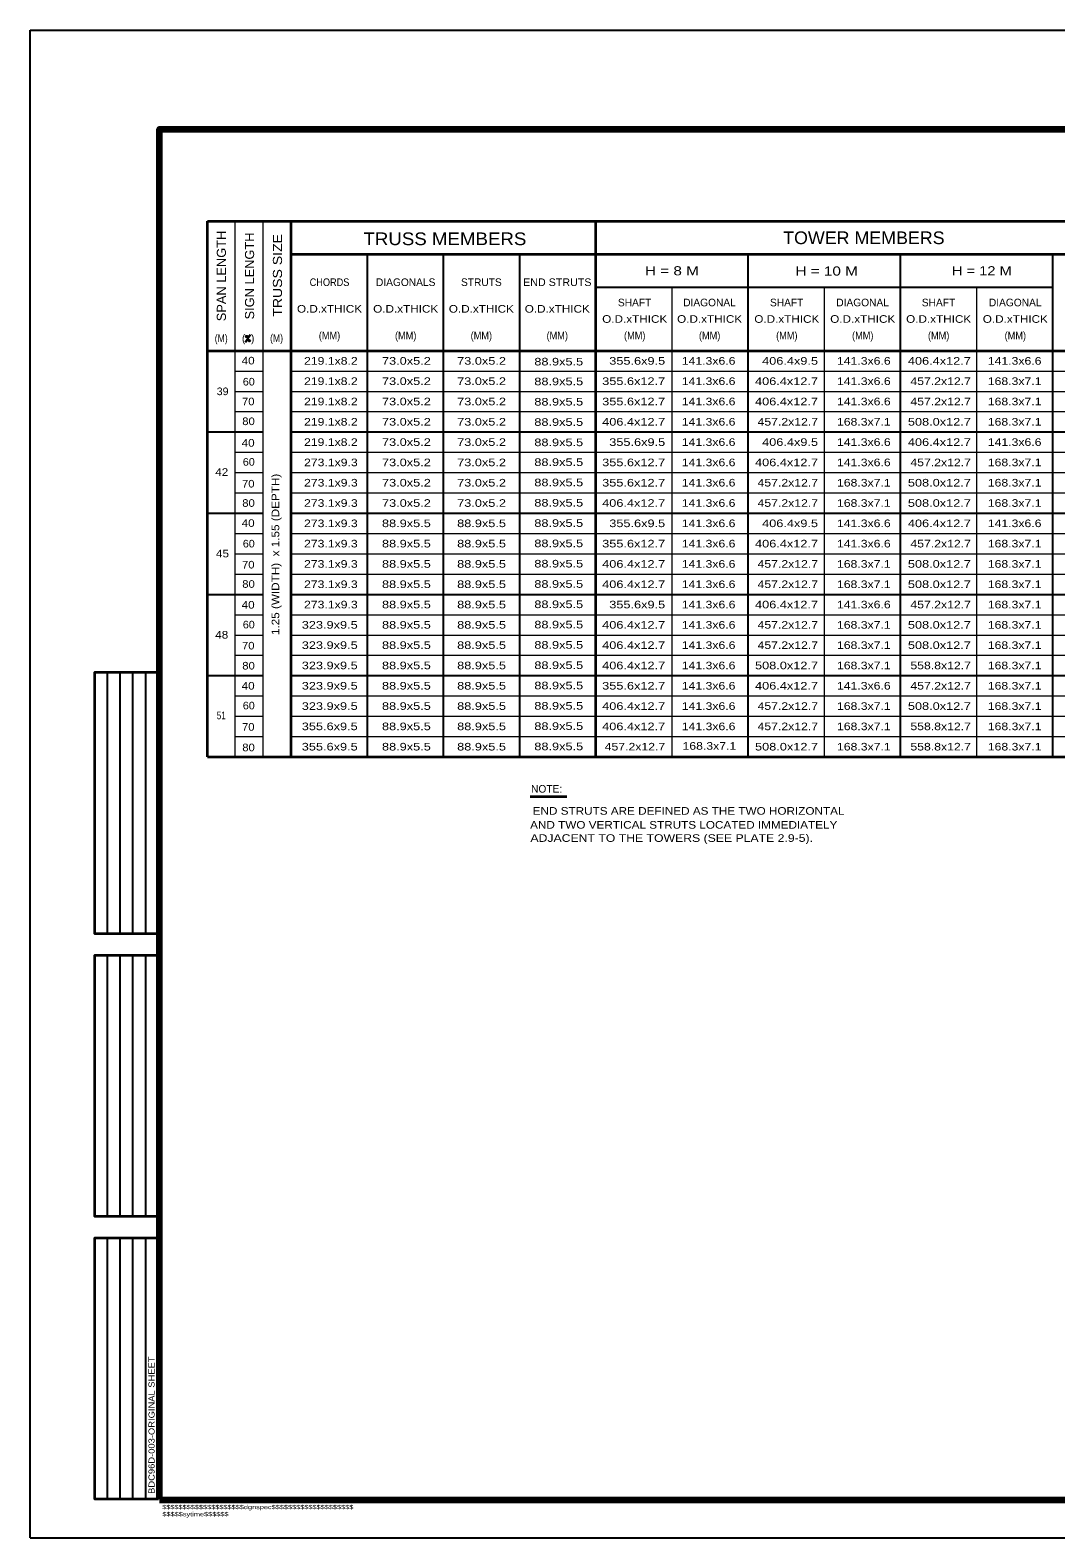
# Model space of a CAD drawing. Extents: x 312601.858 to 312602.699, y 144420.109 to 144420.703.
# Drawn here: x 312601.858 to 312602.262, y 144420.109 to 144420.703 of the extents above; entities that cross this region are included whole.
import ezdxf
from ezdxf.enums import TextEntityAlignment as Align

# ---------------------------------------------------------------- set-up
doc = ezdxf.new("R2010")
doc.units = 0
doc.header["$LTSCALE"] = 0.0012
for name, color, linetype, lineweight in [('1', 7, 'Continuous', 13), ('2', 7, 'Continuous', 35), ('39', 7, 'Continuous', 35), ('60', 7, 'Continuous', 25)]:
    doc.layers.add(name, color=color, linetype=linetype, lineweight=lineweight)

msp = doc.modelspace()

# ---------------------------------------------------------------- linework, layer by layer
at = {"layer": '1', "lineweight": 35}
for p, q in [((312601.9277, 144420.417), (312601.9277, 144420.628)), ((312601.9277, 144420.628), (312602.6681, 144420.628)), ((312601.9607, 144420.417), (312601.9607, 144420.628)), ((312602.0807, 144420.417), (312602.0807, 144420.628)), ((312601.9607, 144420.615), (312602.6357, 144420.615)), ((312601.9277, 144420.577), (312602.6681, 144420.577)), ((312601.9277, 144420.417), (312602.6681, 144420.417))]:
    msp.add_line(p, q, dxfattribs=at)
at = {"layer": '1'}
for p, q in [((312601.9387, 144420.417), (312601.9387, 144420.628)), ((312601.9497, 144420.417), (312601.9497, 144420.628)), ((312602.1107, 144420.417), (312602.1107, 144420.602)), ((312602.1707, 144420.417), (312602.1707, 144420.602)), ((312602.2307, 144420.417), (312602.2307, 144420.602)), ((312602.0357, 144420.577), (312602.2157, 144420.577)), ((312602.0357, 144420.577), (312602.2157, 144420.577)), ((312601.9387, 144420.569), (312601.9497, 144420.569)), ((312601.9607, 144420.569), (312602.6357, 144420.569)), ((312601.9387, 144420.561), (312601.9497, 144420.561)), ((312601.9609, 144420.561), (312602.6357, 144420.561)), ((312601.9387, 144420.553), (312601.9497, 144420.553)), ((312601.9609, 144420.553), (312602.6357, 144420.553)), ((312601.9387, 144420.537), (312601.9497, 144420.537)), ((312601.9387, 144420.537), (312601.949, 144420.537)), ((312601.9609, 144420.537), (312602.6357, 144420.537)), ((312601.9387, 144420.529), (312601.9497, 144420.529)), ((312601.9609, 144420.529), (312602.6357, 144420.529)), ((312601.9387, 144420.521), (312601.9497, 144420.521)), ((312601.9609, 144420.521), (312602.6357, 144420.521)), ((312601.9387, 144420.505), (312601.9497, 144420.505)), ((312601.9609, 144420.505), (312602.6357, 144420.505)), ((312601.9387, 144420.497), (312601.9497, 144420.497)), ((312601.9609, 144420.497), (312602.6357, 144420.497)), ((312601.9387, 144420.489), (312601.9497, 144420.489)), ((312601.9609, 144420.489), (312602.6357, 144420.489)), ((312601.9387, 144420.473), (312601.9497, 144420.473)), ((312601.9609, 144420.473), (312602.6357, 144420.473)), ((312601.9387, 144420.465), (312601.9497, 144420.465)), ((312601.9609, 144420.465), (312602.6357, 144420.465)), ((312601.9387, 144420.457), (312601.9497, 144420.457)), ((312601.9609, 144420.457), (312602.6357, 144420.457)), ((312601.9387, 144420.441), (312601.9497, 144420.441)), ((312601.9609, 144420.441), (312602.6357, 144420.441)), ((312601.9387, 144420.433), (312601.9497, 144420.433)), ((312601.9609, 144420.433), (312602.6357, 144420.433)), ((312601.9387, 144420.425), (312601.9497, 144420.425)), ((312601.9609, 144420.425), (312602.6357, 144420.425))]:
    msp.add_line(p, q, dxfattribs=at)
at = {"layer": '1', "lineweight": 25}
for p, q in [((312601.9907, 144420.417), (312601.9907, 144420.615)), ((312602.0207, 144420.417), (312602.0207, 144420.615)), ((312602.0507, 144420.417), (312602.0507, 144420.615)), ((312602.1407, 144420.417), (312602.1407, 144420.615)), ((312602.2007, 144420.417), (312602.2007, 144420.615)), ((312602.2607, 144420.417), (312602.2607, 144420.615)), ((312602.0807, 144420.602), (312602.2607, 144420.602)), ((312601.9427, 144420.5804), (312601.9447, 144420.5834)), ((312601.9277, 144420.545), (312601.9497, 144420.545)), ((312601.9609, 144420.545), (312602.6357, 144420.545)), ((312601.9277, 144420.513), (312601.9497, 144420.513)), ((312601.9609, 144420.513), (312602.6357, 144420.513)), ((312601.9277, 144420.481), (312601.9497, 144420.481)), ((312601.9609, 144420.481), (312602.6357, 144420.481)), ((312601.9277, 144420.449), (312601.9497, 144420.449)), ((312601.9609, 144420.449), (312602.6357, 144420.449))]:
    msp.add_line(p, q, dxfattribs=at)
for centre in [(312601.9432, 144420.5826), (312601.9442, 144420.581)]:
    msp.add_circle(centre, 0.0003, dxfattribs=at)
at = {"layer": '2'}
msp.add_line((312602.0548, 144420.4014), (312602.0693, 144420.4014), dxfattribs=at)
at = {"layer": '39', "lineweight": 25}
for p, q in [((312601.8579, 144420.7033), (312602.6989, 144420.7033)), ((312601.8579, 144420.1093), (312601.8579, 144420.7033))]:
    msp.add_line(p, q, dxfattribs=at)
msp.add_lwpolyline([(312601.8579, 144420.1093), (312602.6989, 144420.1093), (312602.6989, 144420.7033)], dxfattribs=at)
at = {"layer": '39', "lineweight": 158}
for points in [[(312601.9089, 144420.1243), (312602.6839, 144420.1243), (312602.6839, 144420.6643)], [(312601.9089, 144420.1245), (312601.9089, 144420.6643), (312602.6839, 144420.6643)]]:
    msp.add_lwpolyline(points, dxfattribs=at)
at = {"layer": '60'}
for p, q in [((312601.8884, 144420.3473), (312601.8884, 144420.4503)), ((312601.8934, 144420.3473), (312601.8934, 144420.4503)), ((312601.8984, 144420.3473), (312601.8984, 144420.4503)), ((312601.9035, 144420.3473), (312601.9035, 144420.4503)), ((312601.8884, 144420.2359), (312601.8884, 144420.3389)), ((312601.8934, 144420.2359), (312601.8934, 144420.3389)), ((312601.8984, 144420.2359), (312601.8984, 144420.3389)), ((312601.9035, 144420.2359), (312601.9035, 144420.3389)), ((312601.8884, 144420.1245), (312601.8884, 144420.2275)), ((312601.8934, 144420.1245), (312601.8934, 144420.2275)), ((312601.8984, 144420.1245), (312601.8984, 144420.2275)), ((312601.9035, 144420.1245), (312601.9035, 144420.2275))]:
    msp.add_line(p, q, dxfattribs=at)
at = {"layer": '60', "lineweight": 35}
for points in [[(312601.9085, 144420.3473), (312601.8834, 144420.3473), (312601.8834, 144420.4503), (312601.9085, 144420.4503)], [(312601.9085, 144420.2359), (312601.8834, 144420.2359), (312601.8834, 144420.3389), (312601.9085, 144420.3389)], [(312601.9085, 144420.1245), (312601.8834, 144420.1245), (312601.8834, 144420.2275), (312601.9085, 144420.2275)]]:
    msp.add_lwpolyline(points, dxfattribs=at)

# ---------------------------------------------------------------- texts
at = {"layer": '1'}
for s, height, width, p in [('SPAN LENGTH', 0.0036, 1.05, (312601.935, 144420.60645)), ('SIGN LENGTH', 0.0036, 1.05, (312601.9461, 144420.60645)), ('TRUSS SIZE', 0.0036, 1.15, (312601.9571, 144420.6067)), ('1.25 (WIDTH)  x 1.55 (DEPTH) ', 0.003, 1.15, (312601.956, 144420.4974))]:
    msp.add_text(s, height=height, rotation=90, dxfattribs=dict(at, width=width)).set_placement(p, align=Align.CENTER)
for s, height, width, p in [('TRUSS MEMBERS', 0.005, 1.1, (312602.02125, 144420.6186)), ('TOWER MEMBERS', 0.005, 1.05, (312602.18625, 144420.619)), ('H = 8 M', 0.0036, 1.25, (312602.11065, 144420.6067)), ('H = 10 M', 0.0036, 1.25, (312602.1716, 144420.6066)), ('H = 12 M', 0.0036, 1.2, (312602.2327, 144420.6067)), ('CHORDS', 0.003, 0.9, (312601.9758, 144420.6025)), ('END STRUTS', 0.003, 1.05, (312602.0655, 144420.6025)), ('O.D.xTHICK', 0.003, 1.15, (312601.9758, 144420.592)), ('O.D.xTHICK', 0.003, 1.15, (312602.0058, 144420.592)), ('O.D.xTHICK', 0.003, 1.15, (312602.0356, 144420.592)), ('O.D.xTHICK', 0.003, 1.15, (312602.0655, 144420.592)), ('O.D.xTHICK', 0.003, 1.15, (312602.096, 144420.588)), ('O.D.xTHICK', 0.003, 1.15, (312602.1255, 144420.588)), ('O.D.xTHICK', 0.003, 1.15, (312602.1559, 144420.588)), ('O.D.xTHICK', 0.003, 1.15, (312602.1858, 144420.588)), ('O.D.xTHICK', 0.003, 1.15, (312602.2157, 144420.588)), ('O.D.xTHICK', 0.003, 1.15, (312602.2459, 144420.588)), ('(M)', 0.003, 0.85, (312601.93315, 144420.5804)), ('(M)', 0.003, 0.85, (312601.95495, 144420.5805)), ('(MM)', 0.003, 0.9, (312601.9758, 144420.5815)), ('(MM)', 0.003, 0.9, (312602.0058, 144420.5815)), ('(MM)', 0.003, 0.9, (312602.0356, 144420.5815)), ('(MM)', 0.003, 0.9, (312602.0655, 144420.5815)), ('(MM)', 0.003, 0.9, (312602.096, 144420.5815)), ('(MM)', 0.003, 0.9, (312602.1255, 144420.5815)), ('(MM)', 0.003, 0.9, (312602.1559, 144420.5815)), ('(MM)', 0.003, 0.9, (312602.1858, 144420.5815)), ('(MM)', 0.003, 0.9, (312602.2157, 144420.5815)), ('(MM)', 0.003, 0.9, (312602.2459, 144420.5815)), ('40', 0.003, 1.15, (312601.94375, 144420.5716)), ('141.3x6.6', 0.003, 1.2, (312602.1251, 144420.5715)), ('39', 0.003, 1.05, (312601.9337, 144420.5595)), ('60', 0.003, 1.05, (312601.944, 144420.5633)), ('141.3x6.6', 0.003, 1.2, (312602.1251, 144420.5635)), ('70', 0.003, 1.1, (312601.9438, 144420.5555)), ('141.3x6.6', 0.003, 1.2, (312602.1251, 144420.5555)), ('80', 0.003, 1.1, (312601.9439, 144420.5477)), ('141.3x6.6', 0.003, 1.2, (312602.1251, 144420.5475)), ('40', 0.003, 1.15, (312601.94375, 144420.5392)), ('141.3x6.6', 0.003, 1.2, (312602.1251, 144420.5395)), ('60', 0.003, 1.05, (312601.944, 144420.5317)), ('141.3x6.6', 0.003, 1.2, (312602.1251, 144420.5315)), ('42', 0.003, 1.15, (312601.93335, 144420.5277)), ('70', 0.003, 1.1, (312601.9438, 144420.5231)), ('141.3x6.6', 0.003, 1.2, (312602.1251, 144420.5235)), ('80', 0.003, 1.1, (312601.9439, 144420.5155)), ('141.3x6.6', 0.003, 1.2, (312602.1251, 144420.5155)), ('40', 0.003, 1.15, (312601.94375, 144420.5076)), ('141.3x6.6', 0.003, 1.2, (312602.1251, 144420.5075)), ('45', 0.003, 1.15, (312601.93365, 144420.4956)), ('60', 0.003, 1.05, (312601.944, 144420.4995)), ('141.3x6.6', 0.003, 1.2, (312602.1251, 144420.4995)), ('70', 0.003, 1.1, (312601.9438, 144420.4912)), ('141.3x6.6', 0.003, 1.2, (312602.1251, 144420.4915)), ('80', 0.003, 1.1, (312601.9439, 144420.4836)), ('141.3x6.6', 0.003, 1.2, (312602.1251, 144420.4835)), ('40', 0.003, 1.15, (312601.94375, 144420.4754)), ('141.3x6.6', 0.003, 1.2, (312602.1251, 144420.4755)), ('60', 0.003, 1.05, (312601.944, 144420.4676)), ('141.3x6.6', 0.003, 1.2, (312602.1251, 144420.4675)), ('48', 0.003, 1.15, (312601.93335, 144420.4636)), ('70', 0.003, 1.1, (312601.9438, 144420.4593)), ('141.3x6.6', 0.003, 1.2, (312602.1251, 144420.4595)), ('80', 0.003, 1.1, (312601.9439, 144420.4514)), ('141.3x6.6', 0.003, 1.2, (312602.1251, 144420.4515)), ('40', 0.003, 1.15, (312601.94375, 144420.4435)), ('141.3x6.6', 0.003, 1.2, (312602.1251, 144420.4435)), ('60', 0.003, 1.05, (312601.944, 144420.4357)), ('141.3x6.6', 0.003, 1.2, (312602.1251, 144420.4355)), ('51', 0.003, 0.8, (312601.93315, 144420.4318)), ('70', 0.003, 1.1, (312601.9438, 144420.4273)), ('141.3x6.6', 0.003, 1.2, (312602.1251, 144420.4275)), ('80', 0.003, 1.1, (312601.9439, 144420.4192)), ('168.3x7.1', 0.003, 1.2, (312602.1254, 144420.4198))]:
    msp.add_text(s, height=height, dxfattribs=dict(at, width=width)).set_placement(p, align=Align.CENTER)
for s, p in [('DIAGONALS', (312602.0058, 144420.6025)), ('STRUTS', (312602.0356, 144420.6025)), ('SHAFT', (312602.09595, 144420.5945)), ('DIAGONAL', (312602.12545, 144420.5945)), ('SHAFT', (312602.15585, 144420.5945)), ('DIAGONAL', (312602.18575, 144420.5945)), ('SHAFT', (312602.21565, 144420.5945)), ('DIAGONAL', (312602.24585, 144420.5945)), ('(  )', (312601.94375, 144420.5804)), ('NOTE:', (312602.0613, 144420.4029))]:
    msp.add_text(s, height=0.003, dxfattribs=at).set_placement(p, align=Align.CENTER)
for s, width, p in [('219.1x8.2', 1.2, (312601.9869, 144420.5715)), ('73.0x5.2', 1.25, (312602.0157, 144420.5715)), ('73.0x5.2', 1.25, (312602.0453, 144420.5715)), ('355.6x9.5', 1.25, (312602.108, 144420.5715)), ('406.4x9.5', 1.25, (312602.1682, 144420.5715)), ('141.3x6.6', 1.2, (312602.1968, 144420.5715)), ('406.4x12.7', 1.25, (312602.2284, 144420.5715)), ('141.3x6.6', 1.2, (312602.2562, 144420.5715)), ('219.1x8.2', 1.2, (312601.9869, 144420.5635)), ('73.0x5.2', 1.25, (312602.0157, 144420.5635)), ('73.0x5.2', 1.25, (312602.0453, 144420.5635)), ('355.6x12.7', 1.25, (312602.108, 144420.5635)), ('406.4x12.7', 1.25, (312602.1682, 144420.5635)), ('141.3x6.6', 1.2, (312602.1968, 144420.5635)), ('457.2x12.7', 1.2, (312602.2284, 144420.5635)), ('168.3x7.1', 1.2, (312602.2562, 144420.5635)), ('219.1x8.2', 1.2, (312601.9869, 144420.5555)), ('73.0x5.2', 1.25, (312602.0157, 144420.5555)), ('73.0x5.2', 1.25, (312602.0453, 144420.5555)), ('355.6x12.7', 1.25, (312602.108, 144420.5555)), ('406.4x12.7', 1.25, (312602.1682, 144420.5555)), ('141.3x6.6', 1.2, (312602.1968, 144420.5555)), ('457.2x12.7', 1.2, (312602.2284, 144420.5555)), ('168.3x7.1', 1.2, (312602.2562, 144420.5555)), ('219.1x8.2', 1.2, (312601.9869, 144420.5475)), ('73.0x5.2', 1.25, (312602.0157, 144420.5475)), ('73.0x5.2', 1.25, (312602.0453, 144420.5475)), ('406.4x12.7', 1.25, (312602.108, 144420.5475)), ('457.2x12.7', 1.2, (312602.1682, 144420.5475)), ('168.3x7.1', 1.2, (312602.1968, 144420.5475)), ('508.0x12.7', 1.25, (312602.2284, 144420.5475)), ('168.3x7.1', 1.2, (312602.2562, 144420.5475)), ('219.1x8.2', 1.2, (312601.9869, 144420.5395)), ('73.0x5.2', 1.25, (312602.0157, 144420.5395)), ('73.0x5.2', 1.25, (312602.0453, 144420.5395)), ('355.6x9.5', 1.25, (312602.108, 144420.5395)), ('406.4x9.5', 1.25, (312602.1682, 144420.5395)), ('141.3x6.6', 1.2, (312602.1968, 144420.5395)), ('406.4x12.7', 1.25, (312602.2284, 144420.5395)), ('141.3x6.6', 1.2, (312602.2562, 144420.5395)), ('273.1x9.3', 1.2, (312601.9869, 144420.5315)), ('73.0x5.2', 1.25, (312602.0157, 144420.5315)), ('73.0x5.2', 1.25, (312602.0453, 144420.5315)), ('355.6x12.7', 1.25, (312602.108, 144420.5315)), ('406.4x12.7', 1.25, (312602.1682, 144420.5315)), ('141.3x6.6', 1.2, (312602.1968, 144420.5315)), ('457.2x12.7', 1.2, (312602.2284, 144420.5315)), ('168.3x7.1', 1.2, (312602.2562, 144420.5315)), ('273.1x9.3', 1.2, (312601.9869, 144420.5235)), ('73.0x5.2', 1.25, (312602.0157, 144420.5235)), ('73.0x5.2', 1.25, (312602.0453, 144420.5235)), ('355.6x12.7', 1.25, (312602.108, 144420.5235)), ('457.2x12.7', 1.2, (312602.1682, 144420.5235)), ('168.3x7.1', 1.2, (312602.1968, 144420.5235)), ('508.0x12.7', 1.25, (312602.2284, 144420.5235)), ('168.3x7.1', 1.2, (312602.2562, 144420.5235)), ('273.1x9.3', 1.2, (312601.9869, 144420.5155)), ('73.0x5.2', 1.25, (312602.0157, 144420.5155)), ('73.0x5.2', 1.25, (312602.0453, 144420.5155)), ('406.4x12.7', 1.25, (312602.108, 144420.5155)), ('457.2x12.7', 1.2, (312602.1682, 144420.5155)), ('168.3x7.1', 1.2, (312602.1968, 144420.5155)), ('508.0x12.7', 1.25, (312602.2284, 144420.5155)), ('168.3x7.1', 1.2, (312602.2562, 144420.5155)), ('273.1x9.3', 1.2, (312601.9869, 144420.5075)), ('88.9x5.5', 1.25, (312602.0157, 144420.5075)), ('88.9x5.5', 1.25, (312602.0453, 144420.5075)), ('355.6x9.5', 1.25, (312602.108, 144420.5075)), ('406.4x9.5', 1.25, (312602.1682, 144420.5075)), ('141.3x6.6', 1.2, (312602.1968, 144420.5075)), ('406.4x12.7', 1.25, (312602.2284, 144420.5075)), ('141.3x6.6', 1.2, (312602.2562, 144420.5075)), ('273.1x9.3', 1.2, (312601.9869, 144420.4995)), ('88.9x5.5', 1.25, (312602.0157, 144420.4995)), ('88.9x5.5', 1.25, (312602.0453, 144420.4995)), ('355.6x12.7', 1.25, (312602.108, 144420.4995)), ('406.4x12.7', 1.25, (312602.1682, 144420.4995)), ('141.3x6.6', 1.2, (312602.1968, 144420.4995)), ('457.2x12.7', 1.2, (312602.2284, 144420.4995)), ('168.3x7.1', 1.2, (312602.2562, 144420.4995)), ('273.1x9.3', 1.2, (312601.9869, 144420.4915)), ('88.9x5.5', 1.25, (312602.0157, 144420.4915)), ('88.9x5.5', 1.25, (312602.0453, 144420.4915)), ('406.4x12.7', 1.25, (312602.108, 144420.4915)), ('457.2x12.7', 1.2, (312602.1682, 144420.4915)), ('168.3x7.1', 1.2, (312602.1968, 144420.4915)), ('508.0x12.7', 1.25, (312602.2284, 144420.4915)), ('168.3x7.1', 1.2, (312602.2562, 144420.4915)), ('273.1x9.3', 1.2, (312601.9869, 144420.4835)), ('88.9x5.5', 1.25, (312602.0157, 144420.4835)), ('88.9x5.5', 1.25, (312602.0453, 144420.4835)), ('406.4x12.7', 1.25, (312602.108, 144420.4835)), ('457.2x12.7', 1.2, (312602.1682, 144420.4835)), ('168.3x7.1', 1.2, (312602.1968, 144420.4835)), ('508.0x12.7', 1.25, (312602.2284, 144420.4835)), ('168.3x7.1', 1.2, (312602.2562, 144420.4835)), ('273.1x9.3', 1.2, (312601.9869, 144420.4755)), ('88.9x5.5', 1.25, (312602.0157, 144420.4755)), ('88.9x5.5', 1.25, (312602.0453, 144420.4755)), ('355.6x9.5', 1.25, (312602.108, 144420.4755)), ('406.4x12.7', 1.25, (312602.1682, 144420.4755)), ('141.3x6.6', 1.2, (312602.1968, 144420.4755)), ('457.2x12.7', 1.2, (312602.2284, 144420.4755)), ('168.3x7.1', 1.2, (312602.2562, 144420.4755)), ('323.9x9.5', 1.25, (312601.9869, 144420.4675)), ('88.9x5.5', 1.25, (312602.0157, 144420.4675)), ('88.9x5.5', 1.25, (312602.0453, 144420.4675)), ('406.4x12.7', 1.25, (312602.108, 144420.4675)), ('457.2x12.7', 1.2, (312602.1682, 144420.4675)), ('168.3x7.1', 1.2, (312602.1968, 144420.4675)), ('508.0x12.7', 1.25, (312602.2284, 144420.4675)), ('168.3x7.1', 1.2, (312602.2562, 144420.4675)), ('323.9x9.5', 1.25, (312601.9869, 144420.4595)), ('88.9x5.5', 1.25, (312602.0157, 144420.4595)), ('88.9x5.5', 1.25, (312602.0453, 144420.4595)), ('406.4x12.7', 1.25, (312602.108, 144420.4595)), ('457.2x12.7', 1.2, (312602.1682, 144420.4595)), ('168.3x7.1', 1.2, (312602.1968, 144420.4595)), ('508.0x12.7', 1.25, (312602.2284, 144420.4595)), ('168.3x7.1', 1.2, (312602.2562, 144420.4595)), ('323.9x9.5', 1.25, (312601.9869, 144420.4515)), ('88.9x5.5', 1.25, (312602.0157, 144420.4515)), ('88.9x5.5', 1.25, (312602.0453, 144420.4515)), ('406.4x12.7', 1.25, (312602.108, 144420.4515)), ('508.0x12.7', 1.25, (312602.1682, 144420.4515)), ('168.3x7.1', 1.2, (312602.1968, 144420.4515)), ('558.8x12.7', 1.2, (312602.2284, 144420.4515)), ('168.3x7.1', 1.2, (312602.2562, 144420.4515)), ('323.9x9.5', 1.25, (312601.9869, 144420.4435)), ('88.9x5.5', 1.25, (312602.0157, 144420.4435)), ('88.9x5.5', 1.25, (312602.0453, 144420.4435)), ('355.6x12.7', 1.25, (312602.108, 144420.4435)), ('406.4x12.7', 1.25, (312602.1682, 144420.4435)), ('141.3x6.6', 1.2, (312602.1968, 144420.4435)), ('457.2x12.7', 1.2, (312602.2284, 144420.4435)), ('168.3x7.1', 1.2, (312602.2562, 144420.4435)), ('323.9x9.5', 1.25, (312601.9869, 144420.4355)), ('88.9x5.5', 1.25, (312602.0157, 144420.4355)), ('88.9x5.5', 1.25, (312602.0453, 144420.4355)), ('406.4x12.7', 1.25, (312602.108, 144420.4355)), ('457.2x12.7', 1.2, (312602.1682, 144420.4355)), ('168.3x7.1', 1.2, (312602.1968, 144420.4355)), ('508.0x12.7', 1.25, (312602.2284, 144420.4355)), ('168.3x7.1', 1.2, (312602.2562, 144420.4355)), ('355.6x9.5', 1.25, (312601.9869, 144420.4275)), ('88.9x5.5', 1.25, (312602.0157, 144420.4275)), ('88.9x5.5', 1.25, (312602.0453, 144420.4275)), ('406.4x12.7', 1.25, (312602.108, 144420.4275)), ('457.2x12.7', 1.2, (312602.1682, 144420.4275)), ('168.3x7.1', 1.2, (312602.1968, 144420.4275)), ('558.8x12.7', 1.2, (312602.2284, 144420.4275)), ('168.3x7.1', 1.2, (312602.2562, 144420.4275)), ('355.6x9.5', 1.25, (312601.9869, 144420.4195)), ('88.9x5.5', 1.25, (312602.0157, 144420.4195)), ('88.9x5.5', 1.25, (312602.0453, 144420.4195)), ('457.2x12.7', 1.2, (312602.108, 144420.4195)), ('508.0x12.7', 1.25, (312602.1682, 144420.4195)), ('168.3x7.1', 1.2, (312602.1968, 144420.4195)), ('558.8x12.7', 1.2, (312602.2284, 144420.4195)), ('168.3x7.1', 1.2, (312602.2562, 144420.4195)), ('END STRUTS ARE DEFINED AS THE TWO HORIZONTAL', 1.15, (312602.1786, 144420.3942)), ('AND TWO VERTICAL STRUTS LOCATED IMMEDIATELY', 1.15, (312602.1758, 144420.3887)), ('ADJACENT TO THE TOWERS (SEE PLATE 2.9-5).', 1.2, (312602.1662, 144420.3835))]:
    msp.add_text(s, height=0.003, dxfattribs=dict(at, width=width)).set_placement(p, align=Align.RIGHT)
at = {"layer": '2', "width": 1.25}
for p in [(312602.0757, 144420.5712), (312602.0757, 144420.5634), (312602.0757, 144420.5554), (312602.0757, 144420.5474), (312602.0757, 144420.5394), (312602.0757, 144420.5316), (312602.0757, 144420.5236), (312602.0757, 144420.5156), (312602.0757, 144420.5076), (312602.0757, 144420.4996), (312602.0757, 144420.4916), (312602.0757, 144420.4836), (312602.0757, 144420.4756), (312602.0757, 144420.4676), (312602.0757, 144420.4596), (312602.0757, 144420.4516), (312602.0757, 144420.4436), (312602.0757, 144420.4356), (312602.0757, 144420.4276), (312602.0757, 144420.4196)]:
    msp.add_text('88.9x5.5', height=0.003, dxfattribs=at).set_placement(p, align=Align.RIGHT)
at = {"layer": '2', "width": 1.15}
msp.add_text('BDC96D-003-ORIGINAL SHEET', height=0.0024, rotation=90, dxfattribs=at).set_placement((312601.9069, 144420.1537), align=Align.CENTER)
at = {"layer": '2', "width": 1.3}
for s, p in [('$$$$$$$$$$$$$$$$$$$$dgnspec$$$$$$$$$$$$$$$$$$$$', (312601.9099, 144420.1206)), ('$$$$$sytime$$$$$$', (312601.91, 144420.1178))]:
    msp.add_text(s, height=0.001664, dxfattribs=at).set_placement(p)

doc.saveas('drawing.dxf')
